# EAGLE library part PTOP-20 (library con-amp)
AMP connector
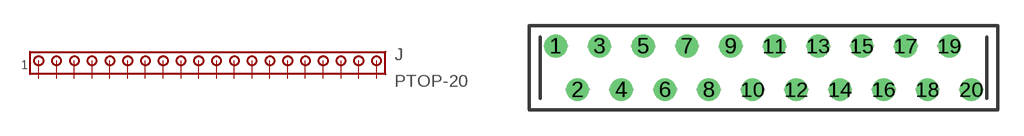
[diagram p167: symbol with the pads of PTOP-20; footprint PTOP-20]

Designator prefix J

## PTOP-20 (OC_FARNELL: unknown; OC_NEWARK: unknown)  [PTOP-20]
1  1  pas
2  2  pas
3  3  pas
4  4  pas
5  5  pas
6  6  pas
7  7  pas
8  8  pas
9  9  pas
10  10  pas
11  11  pas
12  12  pas
13  13  pas
14  14  pas
15  15  pas
16  16  pas
17  17  pas
18  18  pas
19  19  pas
20  20  pas

## Footprint PTOP-20 (pad centres in mm)
AMP connector
drill 0.813 round: 1 -12.065,1.27; 2 -10.795,-1.27; 3 -9.525,1.27; 4 -8.255,-1.27; 5 -6.985,1.27; 6 -5.715,-1.27; 7 -4.445,1.27; 8 -3.175,-1.27; 9 -1.905,1.27; 10 -0.635,-1.27; 11 0.635,1.27; 12 1.905,-1.27; 13 3.175,1.27; 14 4.445,-1.27; 15 5.715,1.27; 16 6.985,-1.27; 17 8.255,1.27; 18 9.525,-1.27; 19 10.795,1.27; 20 12.065,-1.27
